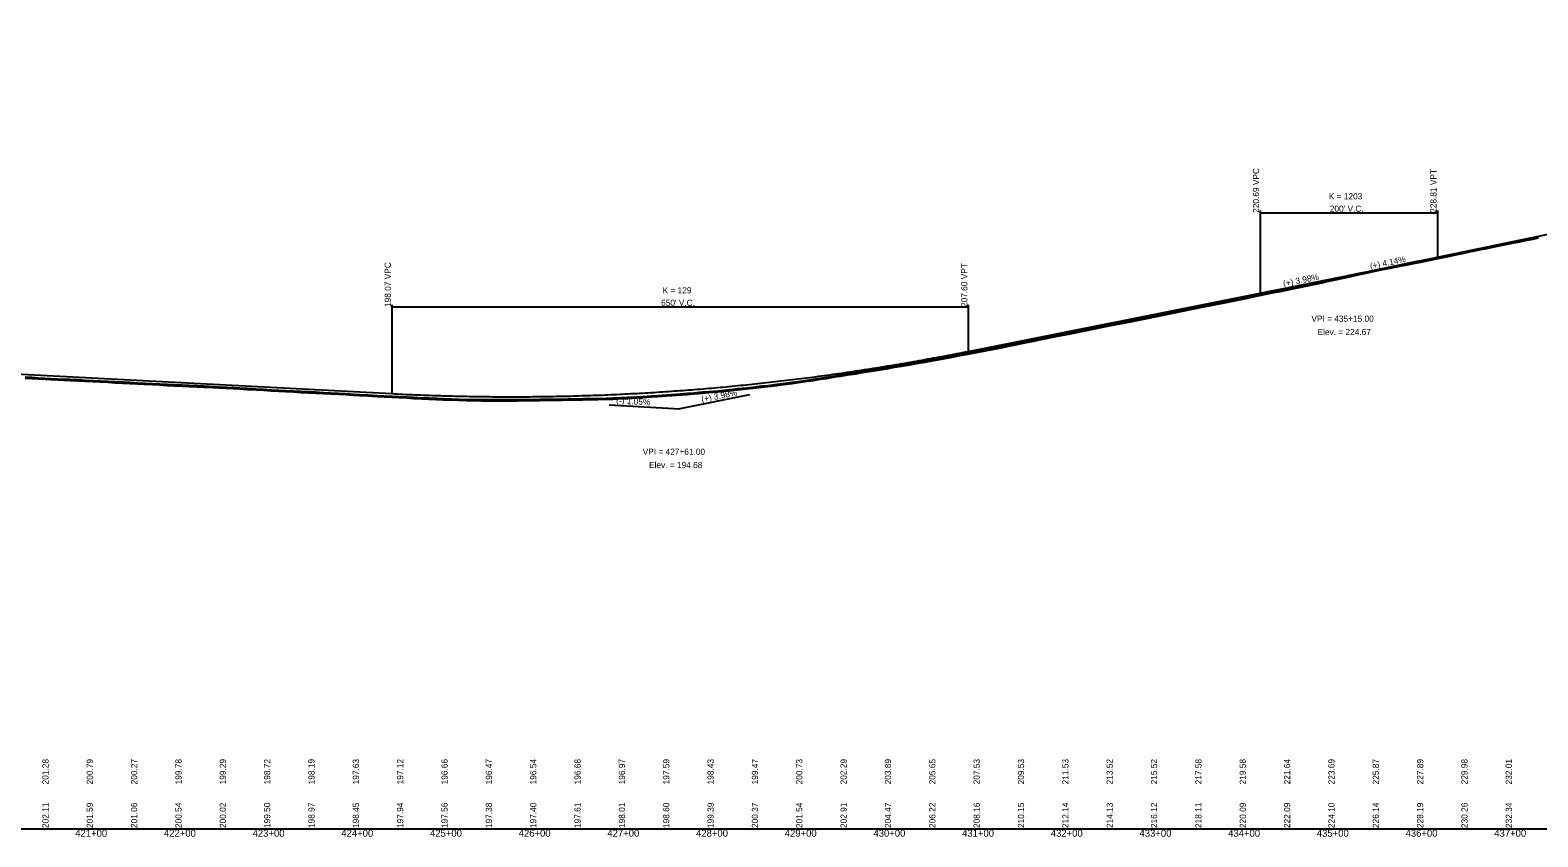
# Model space of a CAD drawing. Extents: x 1876258 to 1926563, y 729739 to 834437.
# Drawn here: x 1920391 to 1922091, y 827954 to 828863 of the extents above; entities that cross this region are included whole.
import ezdxf

# ---------------------------------------------------------------- set-up
doc = ezdxf.new("R2010")
doc.units = 0
for name, color, linetype in [('RD_EX_BldgApp', 7, 'Continuous'), ('RD_EX_H2O_BlueLn', 7, 'Continuous'), ('RD_EX_RailRoad', 7, 'Continuous'), ('RD_HC_Data', 7, 'Continuous'), ('RD_HC_Data_Tic', 7, 'Continuous'), ('RD_HC_TX_Sta50', 7, 'Continuous'), ('RD_PD_ALT3_CL', 7, 'Continuous'), ('RD_PD_ALT5_CL', 7, 'Continuous'), ('RD_PD_Final_Cl', 7, 'Continuous')]:
    doc.layers.add(name, color=color, linetype=linetype)

msp = doc.modelspace()

# ---------------------------------------------------------------- linework, layer by layer
at = {"layer": 'RD_EX_BldgApp'}
for points in [[(1921993.6, 828608.6), (1922000.5, 828609.9), (1922007.9, 828611.6), (1922015.3, 828613.2), (1922018.5, 828613.8), (1922026.8, 828615.5), (1922033.7, 828616.9), (1922042, 828618.6), (1922047.2, 828619.7), (1922055.4, 828621.3), (1922062.3, 828622.7), (1922070.5, 828624.3), (1922077.4, 828625.7), (1922085.6, 828627.3), (1922092.2, 828628.6)], [(1921091.8, 828449.4), (1921099.2, 828449.8), (1921108.8, 828450.5), (1921114.8, 828450.9), (1921120.1, 828451.3), (1921132.5, 828452.3), (1921139.7, 828452.9), (1921149.6, 828453.8), (1921156.8, 828454.4), (1921166.7, 828455.3), (1921173.9, 828456), (1921183.8, 828457), (1921189.2, 828457.5), (1921199, 828458.6), (1921206.2, 828459.3), (1921216.3, 828460.5), (1921223.3, 828461.3), (1921233.4, 828462.5), (1921240.4, 828463.4), (1921250.5, 828464.7), (1921257.5, 828465.6), (1921267.6, 828467.1), (1921274.6, 828468.1), (1921282.1, 828469.3), (1921289.2, 828470.4), (1921300.9, 828472.3), (1921305.3, 828473), (1921312.8, 828474.2), (1921322.6, 828475.6), (1921325.9, 828476.2), (1921332, 828477.2), (1921340, 828478.4), (1921349.3, 828480), (1921357, 828481.2), (1921366.1, 828482.8), (1921374, 828484.1), (1921383.1, 828485.7), (1921390.9, 828487), (1921400.1, 828488.7), (1921407.9, 828490.1), (1921414.8, 828491.4), (1921422.6, 828492.8), (1921432.7, 828494.6), (1921439.8, 828496), (1921448.5, 828497.7), (1921478.1, 828503.4), (1921486.2, 828504.9), (1921494.5, 828506.6), (1921502.1, 828508.2), (1921513, 828510.4), (1921518.7, 828511.6), (1921523, 828512.4), (1921527.6, 828513.4), (1921535.1, 828515), (1921544, 828516.8), (1921551.5, 828518.3), (1921560.4, 828519.9), (1921567.9, 828521.4), (1921576.8, 828523.3), (1921582.4, 828524.4), (1921593.3, 828526.5), (1921600.5, 828527.9), (1921610, 828529.8), (1921633.9, 828534.5), (1921641.2, 828536), (1921648.5, 828537.4), (1921679.9, 828543.9), (1921699.8, 828548), (1921707.4, 828549.6), (1921714.2, 828550.9), (1921723.2, 828552.6), (1921730.3, 828553.9), (1921740, 828555.9), (1921746.9, 828557.4), (1921756.4, 828559.4), (1921764.1, 828560.9), (1921770.3, 828562.2), (1921793.7, 828567), (1921800.7, 828568.3), (1921807.8, 828569.9), (1921814.9, 828571.4), (1921840.7, 828576.7), (1921847.9, 828578.1), (1921852.1, 828579), (1921857.4, 828580.1), (1921864.7, 828581.6), (1921873.6, 828583.5), (1921882, 828585.4), (1921890.3, 828587.3), (1921899.4, 828589.3), (1921907.6, 828591), (1921916.6, 828592.9), (1921925, 828594.6), (1921934, 828596.5), (1921942.3, 828598.1), (1921951.3, 828599.9), (1921959.6, 828601.5), (1921968, 828603.3), (1921976.9, 828605.1), (1921984.8, 828606.7), (1921993.6, 828608.6)], [(1920385.6, 828470.7), (1920393.3, 828470.3), (1920400.6, 828469.9), (1920408.3, 828469.4), (1920414.2, 828469.2), (1920422.2, 828468.8), (1920429.9, 828468.4), (1920436.7, 828468.1), (1920445.8, 828467.7), (1920453.5, 828467.3), (1920462.5, 828466.8), (1920470.2, 828466.4), (1920479.2, 828465.9), (1920486.9, 828465.5), (1920495.8, 828465.1), (1920503.6, 828464.7), (1920512.5, 828464.2), (1920520.4, 828463.8), (1920529.3, 828463.3), (1920537.1, 828462.9), (1920545.9, 828462.5), (1920553.9, 828462.1), (1920562.6, 828461.7), (1920570.6, 828461.3), (1920579.7, 828460.9), (1920587.5, 828460.6), (1920592.3, 828460.3), (1920597.8, 828459.9), (1920604.1, 828459.6), (1920612.6, 828459.3), (1920620.8, 828458.8), (1920627.8, 828458.4), (1920636, 828458), (1920646.2, 828457.4), (1920654.5, 828456.9), (1920663, 828456.4), (1920671.4, 828455.9), (1920679.8, 828455.4), (1920688.4, 828455), (1920696.6, 828454.6), (1920705.2, 828454.2), (1920713.4, 828453.7), (1920722.1, 828453.3), (1920730.2, 828452.9), (1920738.9, 828452.4), (1920746.9, 828452), (1920755.9, 828451.4), (1920763, 828450.9), (1920772, 828450.5), (1920782.6, 828449.8), (1920790.6, 828449.4), (1920799.4, 828449), (1920807.3, 828448.7), (1920816.1, 828448.3), (1920824, 828447.8), (1920833, 828447.4), (1920840.8, 828447), (1920849.7, 828446.6), (1920857.5, 828446.3), (1920866.6, 828446), (1920874.4, 828445.8), (1920883.3, 828445.5), (1920891, 828445.4), (1920900, 828445.2), (1920907.7, 828445.2), (1920916.9, 828445.2), (1920924.5, 828445.2), (1920933.6, 828445.2), (1920940.8, 828445.2), (1920949.2, 828445.4), (1920957, 828445.4), (1920966, 828445.6), (1920975.4, 828445.7), (1920981.7, 828445.7), (1920991.2, 828445.9), (1920997.8, 828446), (1921007.4, 828446.1), (1921014.7, 828446.2), (1921024.2, 828446.4), (1921031.5, 828446.6), (1921041, 828446.8), (1921048.4, 828447.1), (1921058, 828447.5), (1921065.2, 828447.8), (1921074.9, 828448.3), (1921082.2, 828448.7), (1921091.8, 828449.4)]]:
    msp.add_lwpolyline(points, dxfattribs=at)
at = {"layer": 'RD_EX_H2O_BlueLn'}
for p, q in [((1921778.1, 828659.4), (1921778.1, 828566.3)), ((1921778.1, 828656.9), (1921978.1, 828656.9)), ((1921978.1, 828659.4), (1921978.1, 828606.9)), ((1920799.1, 828553.3), (1920799.1, 828453.2)), ((1920799.1, 828550.8), (1921449.1, 828550.8)), ((1921449.1, 828553.3), (1921449.1, 828500.8))]:
    msp.add_line(p, q, dxfattribs=at)
at = {"layer": 'RD_HC_Data_Tic'}
msp.add_lwpolyline([(1920385.7, 828472), (1920393.3, 828471.6), (1920400.7, 828471.1), (1920408.3, 828470.6), (1920414.2, 828470.4), (1920422.3, 828470), (1920430, 828469.6), (1920436.8, 828469.3), (1920445.9, 828468.9), (1920453.5, 828468.5), (1920462.6, 828468), (1920470.3, 828467.7), (1920479.3, 828467.2), (1920487, 828466.8), (1920495.9, 828466.3), (1920503.7, 828465.9), (1920512.6, 828465.4), (1920520.5, 828465), (1920529.3, 828464.5), (1920537.2, 828464.2), (1920546, 828463.8), (1920553.9, 828463.4), (1920562.7, 828463), (1920570.7, 828462.6), (1920579.7, 828462.2), (1920587.6, 828461.9), (1920592.3, 828461.5), (1920597.9, 828461.2), (1920604.1, 828460.9), (1920612.7, 828460.5), (1920620.9, 828460.1), (1920627.8, 828459.7), (1920636.1, 828459.2), (1920646.3, 828458.6), (1920654.6, 828458.1), (1920663.1, 828457.6), (1920671.5, 828457.1), (1920679.8, 828456.7), (1920688.4, 828456.3), (1920696.6, 828455.8), (1920705.2, 828455.4), (1920713.4, 828455), (1920722.1, 828454.6), (1920730.2, 828454.1), (1920739, 828453.7), (1920747, 828453.2), (1920755.9, 828452.6), (1920763, 828452.2), (1920772.1, 828451.8), (1920782.7, 828451.1), (1920790.7, 828450.7), (1920799.4, 828450.3), (1920807.4, 828449.9), (1920816.2, 828449.5), (1920824.1, 828449.1), (1920833, 828448.6), (1920840.8, 828448.3), (1920849.8, 828447.9), (1920857.6, 828447.6), (1920866.7, 828447.2), (1920874.4, 828447), (1920883.4, 828446.7), (1920891, 828446.6), (1920900, 828446.5), (1920907.7, 828446.4), (1920916.9, 828446.4), (1920924.5, 828446.4), (1920933.6, 828446.4), (1920940.7, 828446.5), (1920949.2, 828446.6), (1920957, 828446.7), (1920966, 828446.8), (1920975.4, 828446.9), (1920981.7, 828447), (1920991.2, 828447.1), (1920997.8, 828447.2), (1921007.4, 828447.3), (1921014.6, 828447.5), (1921024.2, 828447.6), (1921031.5, 828447.8), (1921041, 828448.1), (1921048.4, 828448.3), (1921058, 828448.7), (1921065.2, 828449), (1921074.8, 828449.5), (1921082.1, 828450), (1921091.7, 828450.6), (1921099.1, 828451.1), (1921108.8, 828451.7), (1921114.7, 828452.1), (1921120, 828452.5), (1921132.4, 828453.5), (1921139.6, 828454.1), (1921149.5, 828455), (1921156.7, 828455.7), (1921166.6, 828456.5), (1921173.7, 828457.2), (1921183.7, 828458.3), (1921189.1, 828458.8), (1921198.9, 828459.8), (1921206.1, 828460.6), (1921216.1, 828461.8), (1921223.2, 828462.5), (1921233.2, 828463.7), (1921240.2, 828464.6), (1921250.4, 828466), (1921257.3, 828466.9), (1921267.4, 828468.3), (1921274.4, 828469.3), (1921281.9, 828470.5), (1921289, 828471.6), (1921300.7, 828473.5), (1921305.1, 828474.2), (1921312.6, 828475.4), (1921322.4, 828476.9), (1921325.7, 828477.4), (1921331.8, 828478.4), (1921335.1, 828478.9), (1921339.8, 828479.6), (1921344.5, 828480.4), (1921349.1, 828481.2), (1921353.9, 828482), (1921356.8, 828482.5), (1921363.3, 828483.6), (1921365.9, 828484), (1921372.6, 828485.1), (1921373.8, 828485.3), (1921382, 828486.7), (1921382.9, 828486.9), (1921390.7, 828488.3), (1921391.4, 828488.4), (1921399.9, 828489.9), (1921400.8, 828490), (1921407.6, 828491.3), (1921410.1, 828491.8), (1921414.5, 828492.6), (1921419.5, 828493.5), (1921422.3, 828494.1), (1921428.9, 828495.2), (1921432.4, 828495.9), (1921438.3, 828496.9), (1921439.5, 828497.2), (1921447.7, 828498.8), (1921448.3, 828498.9), (1921457, 828500.6), (1921466.4, 828502.4), (1921475.8, 828504.2), (1921477.8, 828504.6), (1921485.2, 828506), (1921486, 828506.2), (1921494.2, 828507.8), (1921494.6, 828507.9), (1921501.8, 828509.4), (1921503.9, 828509.9), (1921512.8, 828511.7), (1921513.3, 828511.8), (1921518.5, 828512.8), (1921522.7, 828513.6), (1921527.4, 828514.6), (1921534.9, 828516.2), (1921543.8, 828518), (1921551.2, 828519.5), (1921560.1, 828521.2), (1921567.6, 828522.7), (1921576.6, 828524.5), (1921582.1, 828525.6), (1921593.1, 828527.7), (1921600.3, 828529.2), (1921609.8, 828531.1), (1921633.6, 828535.8), (1921641, 828537.2), (1921648.2, 828538.6), (1921679.6, 828545.1), (1921699.5, 828549.2), (1921707.2, 828550.8), (1921714, 828552.1), (1921722.9, 828553.8), (1921730, 828555.2), (1921739.7, 828557.2), (1921746.6, 828558.6), (1921756.2, 828560.6), (1921763.8, 828562.1), (1921770.1, 828563.4), (1921793.4, 828568.2), (1921800.5, 828569.6), (1921807.5, 828571.1), (1921814.6, 828572.6), (1921840.4, 828577.9), (1921847.6, 828579.4), (1921851.9, 828580.3), (1921857.1, 828581.4), (1921864.4, 828582.8), (1921873.3, 828584.7), (1921881.7, 828586.6), (1921890, 828588.5), (1921899.1, 828590.5), (1921907.4, 828592.3), (1921916.4, 828594.1), (1921924.7, 828595.8), (1921933.7, 828597.7), (1921942, 828599.3), (1921951, 828601.1), (1921959.3, 828602.8), (1921967.8, 828604.5), (1921976.6, 828606.3), (1921984.6, 828607.9), (1921993.4, 828609.8), (1922000.2, 828611.2), (1922007.7, 828612.8), (1922015, 828614.4), (1922018.2, 828615), (1922026.6, 828616.7), (1922033.5, 828618.1), (1922041.7, 828619.8), (1922046.9, 828620.9), (1922055.1, 828622.5), (1922062, 828623.9), (1922070.2, 828625.6), (1922077.1, 828626.9), (1922085.3, 828628.5), (1922092, 828629.9)], dxfattribs=at)
at = {"layer": 'RD_HC_TX_Sta50'}
for p, q in [((1921956.4, 828602.4), (1921878.1, 828586.1)), ((1921799.6, 828570.5), (1921878.1, 828586.1)), ((1921202.5, 828451.8), (1921124.1, 828436.2)), ((1921044.2, 828440.4), (1921124.1, 828436.2))]:
    msp.add_line(p, q, dxfattribs=at)
at = {"layer": 'RD_PD_ALT5_CL'}
for p, q in [((1921978.1, 828606.9), (1923213.1, 828862.8)), ((1921449.1, 828500.8), (1921778.1, 828566.3)), ((1920351.1, 828476.6), (1920799.1, 828453.2))]:
    msp.add_line(p, q, dxfattribs=at)
for points in [[(1921778.1, 828566.3), (1921782.1, 828567.1), (1921786.1, 828567.9), (1921790.1, 828568.7), (1921794.1, 828569.4), (1921798.1, 828570.2), (1921802.1, 828571), (1921806.1, 828571.8), (1921810.1, 828572.6), (1921814.1, 828573.4), (1921818.1, 828574.2), (1921822.1, 828575.1), (1921826.1, 828575.9), (1921830.1, 828576.7), (1921834.1, 828577.5), (1921838.1, 828578.3), (1921842.1, 828579.1), (1921846.1, 828579.9), (1921850.1, 828580.7), (1921854.1, 828581.5), (1921858.1, 828582.3), (1921862.1, 828583.1), (1921866.1, 828583.9), (1921870.1, 828584.7), (1921874.1, 828585.5), (1921878.1, 828586.4), (1921882.1, 828587.2), (1921886.1, 828588), (1921890.1, 828588.8), (1921894.1, 828589.6), (1921898.1, 828590.4), (1921902.1, 828591.2), (1921906.1, 828592.1), (1921910.1, 828592.9), (1921914.1, 828593.7), (1921918.1, 828594.5), (1921922.1, 828595.3), (1921926.1, 828596.2), (1921930.1, 828597), (1921934.1, 828597.8), (1921938.1, 828598.6), (1921942.1, 828599.4), (1921946.1, 828600.3), (1921950.1, 828601.1), (1921954.1, 828601.9), (1921958.1, 828602.7), (1921962.1, 828603.6), (1921966.1, 828604.4), (1921970.1, 828605.2), (1921974.1, 828606), (1921978.1, 828606.9)], [(1920799.1, 828453.2), (1920812.1, 828452.5), (1920825.1, 828451.9), (1920838.1, 828451.4), (1920851.1, 828451), (1920864.1, 828450.6), (1920877.1, 828450.3), (1920890.1, 828450), (1920903.1, 828449.8), (1920916.1, 828449.7), (1920929.1, 828449.6), (1920942.1, 828449.6), (1920955.1, 828449.7), (1920968.1, 828449.9), (1920981.1, 828450.1), (1920994.1, 828450.3), (1921007.1, 828450.7), (1921020.1, 828451.1), (1921033.1, 828451.5), (1921046.1, 828452), (1921059.1, 828452.6), (1921072.1, 828453.3), (1921085.1, 828454), (1921098.1, 828454.8), (1921111.1, 828455.7), (1921124.1, 828456.6), (1921137.1, 828457.6), (1921150.1, 828458.6), (1921163.1, 828459.7), (1921176.1, 828460.9), (1921189.1, 828462.2), (1921202.1, 828463.5), (1921215.1, 828464.9), (1921228.1, 828466.3), (1921241.1, 828467.8), (1921254.1, 828469.4), (1921267.1, 828471), (1921280.1, 828472.7), (1921293.1, 828474.5), (1921306.1, 828476.3), (1921319.1, 828478.2), (1921332.1, 828480.2), (1921345.1, 828482.2), (1921358.1, 828484.3), (1921371.1, 828486.5), (1921384.1, 828488.7), (1921397.1, 828491), (1921410.1, 828493.4), (1921423.1, 828495.8), (1921436.1, 828498.3), (1921449.1, 828500.8)]]:
    msp.add_spline(points, degree=3, dxfattribs=at)
at = {"layer": 'RD_PD_Final_Cl'}
msp.add_line((1878363.1, 827962.8), (1926563.1, 827962.8), dxfattribs=at)

# ---------------------------------------------------------------- texts
at = {"layer": 'RD_EX_H2O_BlueLn'}
for s, p in [('K = 1203', (1921855.7, 828672.1)), ("200' V.C.", (1921856.8, 828658.1)), ('K = 129', (1921104.5, 828566.1)), ("650' V.C.", (1921102.8, 828552.1))]:
    msp.add_text(s, height=7, dxfattribs=at).set_placement(p)
at = {"layer": 'RD_EX_RailRoad'}
for s, p in [('220.69 VPC', (1921777.1, 828656.9)), ('228.81 VPT', (1921977.1, 828656.9)), ('198.07 VPC', (1920798.1, 828550.8)), ('207.60 VPT', (1921448.1, 828550.8)), ('201.28', (1920412.1, 828012.8)), ('200.79', (1920462.1, 828012.8)), ('200.27', (1920512.1, 828012.8)), ('199.78', (1920562.1, 828012.8)), ('199.29', (1920612.1, 828012.8)), ('198.72', (1920662.1, 828012.8)), ('198.19', (1920712.1, 828012.8)), ('197.63', (1920762.1, 828012.8)), ('197.12', (1920812.1, 828012.8)), ('196.66', (1920862.1, 828012.8)), ('196.47', (1920912.1, 828012.8)), ('196.54', (1920962.1, 828012.8)), ('196.68', (1921012.1, 828012.8)), ('196.97', (1921062.1, 828012.8)), ('197.59', (1921112.1, 828012.8)), ('198.43', (1921162.1, 828012.8)), ('199.47', (1921212.1, 828012.8)), ('200.73', (1921262.1, 828012.8)), ('202.29', (1921312.1, 828012.8)), ('203.89', (1921362.1, 828012.8)), ('205.65', (1921412.1, 828012.8)), ('207.53', (1921462.1, 828012.8)), ('209.53', (1921512.1, 828012.8)), ('211.53', (1921562.1, 828012.8)), ('213.52', (1921612.1, 828012.8)), ('215.52', (1921662.1, 828012.8)), ('217.58', (1921712.1, 828012.8)), ('219.58', (1921762.1, 828012.8)), ('221.64', (1921812.1, 828012.8)), ('223.69', (1921862.1, 828012.8)), ('225.87', (1921912.1, 828012.8)), ('227.89', (1921962.1, 828012.8)), ('229.98', (1922012.1, 828012.8)), ('232.01', (1922062.1, 828012.8)), ('202.11', (1920412.1, 827963.6)), ('201.59', (1920462.1, 827963.6)), ('201.06', (1920512.1, 827963.6)), ('200.54', (1920562.1, 827963.6)), ('200.02', (1920612.1, 827963.6)), ('199.50', (1920662.1, 827963.6)), ('198.97', (1920712.1, 827963.6)), ('198.45', (1920762.1, 827963.6)), ('197.94', (1920812.1, 827963.6)), ('197.56', (1920862.1, 827963.6)), ('197.38', (1920912.1, 827963.6)), ('197.40', (1920962.1, 827963.6)), ('197.61', (1921012.1, 827963.6)), ('198.01', (1921062.1, 827963.6)), ('198.60', (1921112.1, 827963.6)), ('199.39', (1921162.1, 827963.6)), ('200.37', (1921212.1, 827963.6)), ('201.54', (1921262.1, 827963.6)), ('202.91', (1921312.1, 827963.6)), ('204.47', (1921362.1, 827963.6)), ('206.22', (1921412.1, 827963.6)), ('208.16', (1921462.1, 827963.6)), ('210.15', (1921512.1, 827963.6)), ('212.14', (1921562.1, 827963.6)), ('214.13', (1921612.1, 827963.6)), ('216.12', (1921662.1, 827963.6)), ('218.11', (1921712.1, 827963.6)), ('220.09', (1921762.1, 827963.6)), ('222.09', (1921812.1, 827963.6)), ('224.10', (1921862.1, 827963.6)), ('226.14', (1921912.1, 827963.6)), ('228.19', (1921962.1, 827963.6)), ('230.26', (1922012.1, 827963.6)), ('232.34', (1922062.1, 827963.6))]:
    msp.add_text(s, height=7, rotation=90, dxfattribs=at).set_placement(p)
at = {"layer": 'RD_HC_Data'}
for s, p in [('VPI = 435+15.00', (1921836.1, 828534.1)), ('Elev. = 224.67', (1921843, 828519.1)), ('VPI = 427+61.00', (1921082.1, 828384.2)), ('Elev. = 194.68', (1921089.2, 828369.2))]:
    msp.add_text(s, height=7, dxfattribs=at).set_placement(p)
at = {"layer": 'RD_HC_TX_Sta50'}
for s, rotation, p in [('(+) 4.14%', 11.7064, (1921902.8, 828593.3)), ('(+) 3.98%', 11.2488, (1921804.8, 828573.6)), ('(-) 1.05%', 357.008, (1921052, 828442)), ('(+) 3.98%', 11.2488, (1921148.9, 828443.2))]:
    msp.add_text(s, height=7, rotation=rotation, dxfattribs=at).set_placement(p)
at = {"layer": 'RD_PD_ALT3_CL'}
for s, p in [('421+00', (1920442.2, 827953.8)), ('422+00', (1920542.2, 827953.8)), ('423+00', (1920642.2, 827953.8)), ('424+00', (1920742.2, 827953.8)), ('425+00', (1920842.2, 827953.8)), ('426+00', (1920942.2, 827953.8)), ('427+00', (1921042.2, 827953.8)), ('428+00', (1921142.2, 827953.8)), ('429+00', (1921242.2, 827953.8)), ('430+00', (1921342.2, 827953.8)), ('431+00', (1921442.2, 827953.8)), ('432+00', (1921542.2, 827953.8)), ('433+00', (1921642.2, 827953.8)), ('434+00', (1921742.2, 827953.8)), ('435+00', (1921842.2, 827953.8)), ('436+00', (1921942.2, 827953.8)), ('437+00', (1922042.2, 827953.8))]:
    msp.add_text(s, height=8, dxfattribs=at).set_placement(p)

doc.saveas('drawing.dxf')
